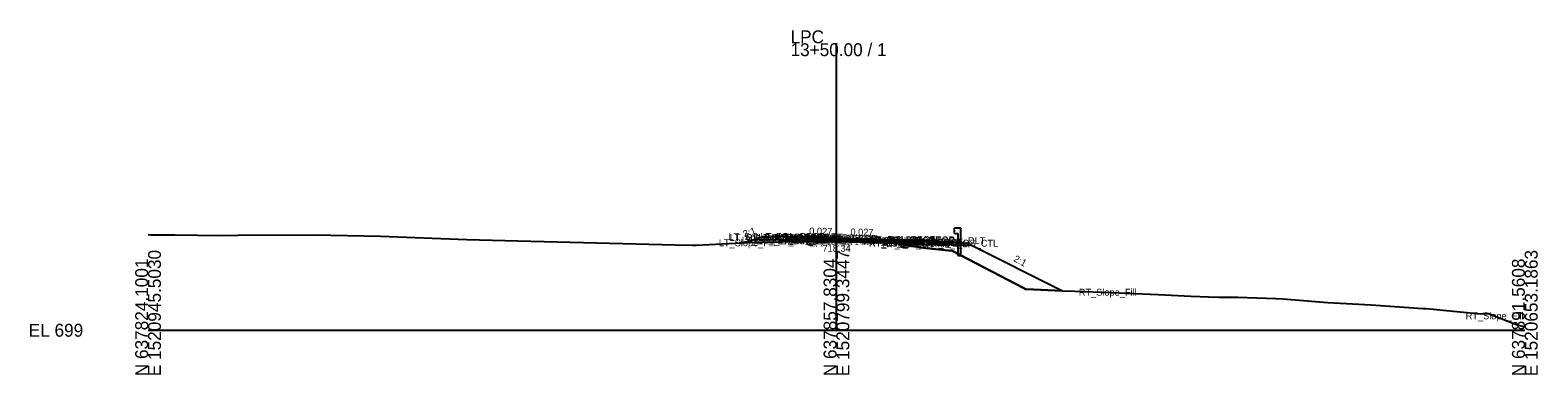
# Model space of a CAD drawing. Extents: x -26 to 303, y -10 to 4521.
# Drawn here: x -25.7 to 302.8, y 3490.3 to 3565.3 of the extents above; entities that cross this region are included whole.
import ezdxf

# ---------------------------------------------------------------- set-up
doc = ezdxf.new("R2010")
doc.units = 0
for name, color, linetype in [('Default', 7, 'Continuous'), ('Exist Cross Section Cell', 7, 'Continuous'), ('Exist XS Center Line Elevation Label', 7, 'Continuous'), ('Exist XS Ground Line', 7, 'Continuous'), ('Prop CMT Guardrail Graphics', 7, 'Continuous'), ('Prop CMT Pvmt Course 1', 7, 'Continuous'), ('Prop CMT Pvmt Course 2', 7, 'Continuous'), ('Prop CMT Pvmt Course 3', 7, 'Continuous'), ('Prop CMT Pvmt Surface', 7, 'Continuous'), ('Prop CMT Pvmt Surface Shoulder', 7, 'Continuous'), ('Prop CMT Shld Paved Course 1', 7, 'Continuous'), ('Prop CMT Shld Paved Course 2', 7, 'Continuous'), ('Prop CMT Shld Paved Course 3', 7, 'Continuous'), ('Prop CMT Slope Grass', 7, 'Continuous'), ('Prop CMT Subgrade Earthwork', 7, 'Continuous'), ('Prop XS Earthwork Shape', 7, 'Continuous'), ('Prop XS Shear Point Element', 7, 'Continuous')]:
    doc.layers.add(name, color=color, linetype=linetype)

msp = doc.modelspace()

# ---------------------------------------------------------------- linework, layer by layer
at = {"layer": 'Exist Cross Section Cell'}
for p, q in [((150, 3500), (150, 3562.46)), ((0, 3500), (150, 3500)), ((150, 3500), (300, 3500))]:
    msp.add_line(p, q, dxfattribs=at)
at = {"layer": 'Exist XS Ground Line'}
msp.add_lwpolyline([(0, 3520.82), (0.65, 3520.78), (5.82, 3520.78), (15.76, 3520.66), (19.62, 3520.67), (36.17, 3520.8), (50.65, 3520.46), (69.46, 3519.78), (80.61, 3519.46), (114.89, 3518.56), (118.64, 3518.51), (119.42, 3518.55), (127.93, 3518.95), (127.95, 3518.95), (130.54, 3519.08), (133.1, 3519.14), (142.37, 3519.34), (142.86, 3519.33), (143.38, 3519.32), (144.91, 3519.32), (146.2, 3519.32), (147.48, 3519.33), (147.87, 3519.33), (150, 3519.35), (150.03, 3519.35), (151.19, 3519.34), (152.59, 3519.33), (154.51, 3519.3), (155.15, 3519.29), (157.24, 3519.26), (157.72, 3519.25), (157.84, 3519.25), (159.91, 3519.22), (160.04, 3519.22), (160.04, 3519.22), (160.56, 3519.18), (161.75, 3519.14), (164.23, 3518.69), (166.52, 3518.29), (169.49, 3517.9), (174.4, 3517.39), (175.25, 3517.31), (190.81, 3509.16), (191.23, 3508.94), (191.33, 3508.94), (199.26, 3508.59), (201.97, 3508.53), (209.85, 3508.2), (214.95, 3508.02), (220.11, 3507.8), (227.22, 3507.41), (231.07, 3507.28), (233.34, 3507.19), (237.45, 3507.17), (245.74, 3506.89), (247.35, 3506.83), (252.64, 3506.39), (256.12, 3506.11), (257.07, 3506.06), (266.49, 3505.54), (277.75, 3504.77), (278.2, 3504.75), (278.49, 3504.72), (280.01, 3504.58), (290.26, 3503.6), (290.88, 3503.64), (292.09, 3503.65), (297.28, 3501.6), (298.36, 3501.19), (299.78, 3500.81), (300, 3500.73)], dxfattribs=at)
at = {"layer": 'Prop CMT Guardrail Graphics'}
for points in [[(177.13, 3522.24), (175.79, 3522.24), (175.52, 3521.95)], [(175.52, 3521.95), (175.79, 3521.66)], [(177.13, 3516.24), (177.13, 3522.24)], [(175.79, 3521.66), (175.52, 3521.37)], [(175.52, 3521.37), (175.79, 3521.07), (176.46, 3521.07)], [(176.46, 3521.07), (176.46, 3516.24)], [(176.46, 3516.24), (177.13, 3516.24)]]:
    msp.add_lwpolyline(points, dxfattribs=at)
at = {"layer": 'Prop CMT Pvmt Course 1'}
msp.add_line((150.07, 3520.13), (163.54, 3519.77), dxfattribs=at)
for points in [[(150.07, 3520.13), (143.53, 3520.31)], [(143.53, 3520.31), (143.53, 3520.06)], [(143.53, 3520.06), (150.07, 3519.88)], [(150.07, 3519.88), (150.07, 3520.13)], [(150.07, 3519.88), (150.07, 3520.13)], [(163.54, 3519.52), (150.07, 3519.88)], [(163.54, 3519.77), (163.54, 3519.52)]]:
    msp.add_lwpolyline(points, dxfattribs=at)
msp.add_lwpolyline([(150.07, 3519.88), (150.07, 3520.01), (150.07, 3520.01), (150.07, 3519.88)], close=True, dxfattribs=at)
msp.add_lwpolyline([(150.07, 3519.88), (150.07, 3520.01), (150.07, 3520.01), (150.07, 3519.88)], close=True, dxfattribs=at)
at = {"layer": 'Prop CMT Pvmt Course 2'}
for points in [[(150.07, 3519.88), (143.53, 3520.06)], [(143.53, 3520.06), (143.53, 3519.73)], [(143.53, 3519.73), (150.07, 3519.55)], [(150.07, 3519.55), (150.07, 3519.88)], [(150.07, 3519.55), (150.07, 3519.88)], [(150.07, 3519.88), (163.54, 3519.52)], [(163.54, 3519.19), (150.07, 3519.55)], [(163.54, 3519.52), (163.54, 3519.19)]]:
    msp.add_lwpolyline(points, dxfattribs=at)
at = {"layer": 'Prop CMT Pvmt Course 3'}
for points in [[(150.07, 3519.55), (143.53, 3519.73)], [(143.53, 3519.73), (143.53, 3519.48)], [(143.53, 3519.48), (150.07, 3519.3)], [(150.07, 3519.3), (150.07, 3519.55)], [(150.07, 3519.55), (163.54, 3519.19)], [(150.07, 3519.3), (150.07, 3519.55)], [(163.54, 3518.94), (150.07, 3519.3)], [(163.54, 3519.19), (163.54, 3518.94)]]:
    msp.add_lwpolyline(points, dxfattribs=at)
at = {"layer": 'Prop CMT Pvmt Surface'}
for points in [[(150.07, 3520.13), (143.53, 3520.31)], [(150.07, 3520.13), (163.54, 3519.77)]]:
    msp.add_lwpolyline(points, dxfattribs=at)
at = {"layer": 'Prop CMT Pvmt Surface Shoulder'}
for points in [[(143.53, 3520.31), (139.53, 3520.41)], [(163.54, 3519.77), (167.54, 3519.67)]]:
    msp.add_lwpolyline(points, dxfattribs=at)
at = {"layer": 'Prop CMT Shld Paved Course 1'}
for p in [(167.81, 3519.4), (175.52, 3519.15)]:
    msp.add_line(p, (175.52, 3518.9), dxfattribs=at)
for points in [[(143.53, 3520.31), (139.53, 3520.41), (139.29, 3520.17)], [(139.29, 3520.17), (143.53, 3520.06)], [(143.53, 3520.06), (143.53, 3520.31)], [(163.54, 3519.77), (167.54, 3519.67), (167.8, 3519.41)], [(163.54, 3519.52), (163.54, 3519.77)], [(167.8, 3519.41), (163.54, 3519.52)]]:
    msp.add_lwpolyline(points, dxfattribs=at)
at = {"layer": 'Prop CMT Shld Paved Course 2'}
for points in [[(143.53, 3520.06), (139.29, 3520.17), (138.97, 3519.85)], [(138.97, 3519.85), (143.53, 3519.73)], [(143.53, 3519.73), (143.53, 3520.06)], [(163.54, 3519.52), (167.8, 3519.41), (168.13, 3519.07)], [(163.54, 3519.19), (163.54, 3519.52)], [(168.13, 3519.07), (163.54, 3519.19)]]:
    msp.add_lwpolyline(points, dxfattribs=at)
at = {"layer": 'Prop CMT Shld Paved Course 3'}
for p, q in [((138.97, 3519.85), (138.72, 3519.61)), ((168.13, 3519.07), (168.39, 3518.81))]:
    msp.add_line(p, q, dxfattribs=at)
for points in [[(138.23, 3519.62), (143.53, 3519.48)], [(143.53, 3519.73), (138.97, 3519.85), (138.72, 3519.61)], [(143.53, 3519.48), (143.53, 3519.73)], [(163.54, 3518.94), (163.54, 3519.19)], [(163.54, 3519.19), (168.13, 3519.07), (168.39, 3518.81)], [(168.89, 3518.8), (163.54, 3518.94)]]:
    msp.add_lwpolyline(points, dxfattribs=at)
at = {"layer": 'Prop CMT Slope Grass'}
for points in [[(139.53, 3520.41), (133.54, 3520.21), (130.06, 3519.05)], [(167.54, 3519.67), (178.55, 3518.96), (199.29, 3508.59)]]:
    msp.add_lwpolyline(points, dxfattribs=at)
at = {"layer": 'Prop CMT Subgrade Earthwork'}
for points in [[(143.53, 3519.48), (132.23, 3519.78)], [(150.07, 3519.3), (143.53, 3519.48)], [(150.07, 3519.3), (163.54, 3518.94)], [(163.54, 3518.94), (179.42, 3518.52)]]:
    msp.add_lwpolyline(points, dxfattribs=at)
at = {"layer": 'Prop XS Earthwork Shape'}
for points in [[(150.07, 3519.3), (143.53, 3519.48), (132.23, 3519.78), (130.06, 3519.05), (130.54, 3519.08), (133.1, 3519.14), (142.37, 3519.34), (142.86, 3519.33), (143.38, 3519.32), (144.91, 3519.32), (146.2, 3519.32), (147.48, 3519.33), (147.87, 3519.33)], [(150.07, 3519.3), (162.71, 3518.97), (161.75, 3519.14), (160.56, 3519.18), (160.04, 3519.22), (159.91, 3519.22), (157.84, 3519.25), (157.72, 3519.25), (157.24, 3519.26), (155.15, 3519.29), (154.51, 3519.3), (152.59, 3519.33), (151.19, 3519.34)], [(163.54, 3518.94), (179.42, 3518.52), (199.29, 3508.59), (191.33, 3508.94), (191.23, 3508.94), (190.81, 3509.16), (175.25, 3517.31), (174.4, 3517.39), (169.49, 3517.9), (166.52, 3518.29), (164.23, 3518.69), (162.71, 3518.97)]]:
    msp.add_lwpolyline(points, close=True, dxfattribs=at)

# ---------------------------------------------------------------- texts
at = {"layer": 'Default'}
msp.add_text('-', height=0.0001, dxfattribs=at).set_placement((0, 3500))
at = {"layer": 'Exist Cross Section Cell'}
for s, p in [('LPC', (140, 3562.46)), ('13+50.00 / 1', (140, 3559.66)), ('EL 699', (-26, 3498.6))]:
    msp.add_text(s, height=2.8, dxfattribs=at).set_placement(p)
for s, p in [('N 637824.1001', (0, 3490)), ('E 1520945.5030', (2.8, 3490)), ('N 637857.8304', (150, 3490)), ('E 1520799.3447', (152.8, 3490)), ('N 637891.5608', (300, 3490)), ('E 1520653.1863', (302.8, 3490))]:
    msp.add_text(s, height=2.8, rotation=90, dxfattribs=at).set_placement(p)
at = {"layer": 'Exist XS Center Line Elevation Label'}
for s, rotation, p in [('3:1', 19.8357, (129.96, 3520.16)), ('0.027', 358.8358, (144.06, 3520.85)), ('0.027', 358.8358, (153.04, 3520.65)), ('2:1', 332.3479, (188.47, 3515.1))]:
    msp.add_text(s, height=1.5, rotation=rotation, dxfattribs=at).set_placement(p)
msp.add_text('718.34', height=1.5, dxfattribs=at).set_placement((146.98, 3517.09))
at = {"layer": 'Prop XS Shear Point Element'}
for s, p in [('LT_Slope_Fill', (124.37, 3518.29)), ('LT_Sub_Trench_Out_DLT', (126.47, 3519.6)), ('LT_GS_OS_CTL', (126.73, 3519.46)), ('LT_Sub_Trench_Out', (129.39, 3518.87)), ('LT_PS3_Shelf_Out', (130.45, 3519.11)), ('LT_PS3_OEOP', (132.65, 3519.1)), ('LT_PS2_OEOP', (132.97, 3519.42)), ('LT_PS1_OEOP', (133.39, 3519.66)), ('LT_PV2_OEOT', (137.15, 3519.31)), ('LT_PV3_OEOT', (137.15, 3518.98)), ('LT_Sub_OEOT', (137.18, 3518.73)), ('LT_PV1_OEOT', (137.33, 3519.56)), ('RT_PV2_OEEOP', (143.07, 3519.13)), ('RT_PV3_OEEOP', (143.07, 3518.8)), ('RT_Sub_OEEOP', (143.11, 3518.55)), ('LT_PV2_OEEOP', (143.16, 3519.13)), ('LT_PV3_OEEOP', (143.16, 3518.8)), ('LT_Sub_OEEOP', (143.2, 3518.55)), ('RT_PV1_OEEOP', (143.25, 3519.26)), ('LT_PV1_OEEOP', (143.34, 3519.26)), ('RT_PV2_IEEOP', (143.64, 3519.13)), ('LT_PV2_IEEOP', (143.73, 3519.13)), ('RT_PV1_IEEOP', (143.82, 3519.26)), ('LT_PV1_IEEOP', (143.91, 3519.26)), ('PV2_PGL', (146.1, 3519.13)), ('PV1_PGL', (146.28, 3519.38)), ('RT_PV2_OEOT', (157.07, 3518.77)), ('RT_PV3_OEOT', (157.07, 3518.44)), ('RT_Sub_OEOT', (157.11, 3518.19)), ('RT_PV1_OEOT', (157.25, 3519.02)), ('RT_Sub_Trench_Out_DLT', (158.48, 3518.75)), ('RT_Sub_Trench_Out', (159.97, 3518.05)), ('RT_PS3_Shelf_Out', (160.53, 3518.31)), ('RT_PS1_OEOP', (161.31, 3518.92)), ('RT_PS2_OEOP', (161.39, 3518.66)), ('RT_PS3_OEOP', (161.73, 3518.32)), ('RT_GS_OS_CTL', (169.64, 3518.2)), ('RT_Slope_Fill', (202.82, 3507.52)), ('RT_Slope_Fill', (287.12, 3502.39))]:
    msp.add_text(s, height=1.5, dxfattribs=at).set_placement(p)

doc.saveas('drawing.dxf')
